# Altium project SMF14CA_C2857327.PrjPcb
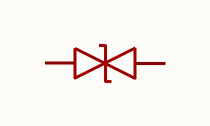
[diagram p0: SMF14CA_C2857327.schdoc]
1 sheet, 1 parts. Net scope: global (net labels, ports and power ports of the same name join across sheets).

## Sheet SMF14CA_C2857327.schdoc
size 127 x 101 mm

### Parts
D?  smf14ca_c2857327  [SOD-123FL_L2.8-W1.8-LS3.7-BI]  (value not drawn)

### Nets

Not connected (* = marked no-connect by the designer): D? 1 2

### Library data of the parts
D? = smf14ca_c2857327: 极性:双向;反向截止电压(Vrwm):14V;钳位电压:23.2V;峰值脉冲电流(Ipp):8.6A;峰值脉冲功率(Ppp):200W@10/1000us;击穿电压(VBR):15.6V;; Manufacturer: JSMSEMI(杰盛微); AddInBom: yes; ModelId: d105299b3871451c86f679efef28ff8f; ModelTransform: 145.669,70.866,0,0,0,0,0,0,0; Polarity: 双向; Reverse Stand-Off Voltage (Vrwm): 14V; Clamping Voltage: 23.2V; Peak Pulse Current (Ipp): 8.6A; Voltage - Breakdown: 15.6V; Reverse Leakage Current (Ir): 1uA; Number of Channels: 单路; Type: TVS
